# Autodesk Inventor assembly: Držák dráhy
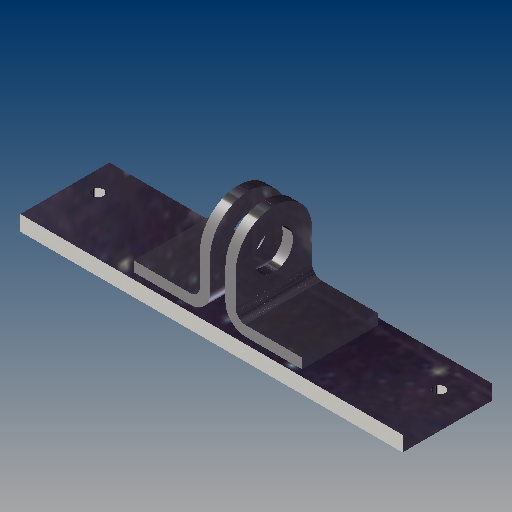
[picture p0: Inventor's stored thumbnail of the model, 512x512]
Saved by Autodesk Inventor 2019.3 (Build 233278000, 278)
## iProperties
Created: 2019-03
Part Number: Držák dráhy
Material: Všeobecné
Document SubType Name: Assembly
Designer: B-hon
Author: B-hon
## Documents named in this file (3)
- C:\Users\B-hon\OneDrive\Plocha\Bakalářka22\Držák dráhy.iam
- C:\Users\B-hon\OneDrive\Plocha\Bakalářka22\Držák čepu.ipt
- C:\Users\B-hon\OneDrive\Plocha\Bakalářka22\Držák dráhy.ipt
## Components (3 placed, 2 different names)
1. Držák čepu:1 — Proti sobě:1, Stejný směr:1, Stejný směr:2, Vložit:1
2. Držák dráhy:1 — Proti sobě:1, Stejný směr:1, Stejný směr:2, Proti sobě:2
3. Držák čepu:2 — Vložit:1, Proti sobě:2
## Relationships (5: Mate 2, Flush 2, Insert 1)
- Proti sobě:1 [Mate]: Držák čepu:1 ↔ Držák dráhy:1
- Stejný směr:1 [Flush]: Držák čepu:1 ↔ Držák dráhy:1
- Stejný směr:2 [Flush]: Držák čepu:1 ↔ Držák dráhy:1
- Vložit:1 [Insert]: Držák čepu:1 ↔ Držák čepu:2
- Proti sobě:2 [Mate]: Držák dráhy:1 ↔ Držák čepu:2
